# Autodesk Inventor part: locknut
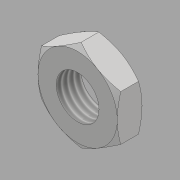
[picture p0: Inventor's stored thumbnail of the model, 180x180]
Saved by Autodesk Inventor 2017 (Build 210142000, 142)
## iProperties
Created: 2016-05
Part Number: locknut
Material: Generic
Document SubType Name: Modeling
Designer: CADCIM
Density: 1 g/cm^3
Appearance: Default
Author: CADCIM
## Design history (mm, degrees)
sketch "Sketch1"
  geometry: L1 (9.6, -5.543)-(0, -11.085); L2 (0, -11.085)-(-9.6, -5.543); L3 (-9.6, -5.543)-(-9.6, 5.543); L4 (-9.6, 5.543)-(0, 11.085); L5 (0, 11.085)-(9.6, 5.543); L6 (9.6, 5.543)-(9.6, -5.543); 2 further points
  constraints: 12 end point, 1 coincident, 1 vertical alignment, 13 other
  dimensions: "d0" = 19.2 distance between parallel lines of L3 L6
extrude "Extrusion1" new body sketch "Sketch1" distance "d1" = 6; taper "d2" = 0 deg
sketch "Sketch2"
  geometry: L1 (0, 11.085)-(-9.6, 5.543) reference; C1 r 9.6 at (0, 0); 1 further point
  constraints: 1 centre point, 1 coincident, 1 tangent
extrude "Extrusion2" sketch "Sketch2" distance "d3" = 10.8; taper "d4" = 60 deg
workplane "Work Plane1"
sketch "Sketch3"
  geometry: L1 (0, -11.085)-(9.6, -5.543) reference; C1 r 9.6 at (0, 0); 1 further point
  constraints: 1 centre point, 1 coincident, 1 tangent
extrude "Extrusion3" sketch "Sketch3" distance "d5" = 10.8; taper "d6" = 60 deg
sketch "Sketch4"
  geometry: 1 further point
hole "Hole1" diameter "d9" = 10.376; stored, may be unused: countersink angle "d13" = 90 deg, drill point angle "d15" = 118 deg; dims "d7" = 10, "d8" = 10, "d10" = 24, "d11" = 4, "d12" = 2, "d14" = 31.3
body "Solid1"
